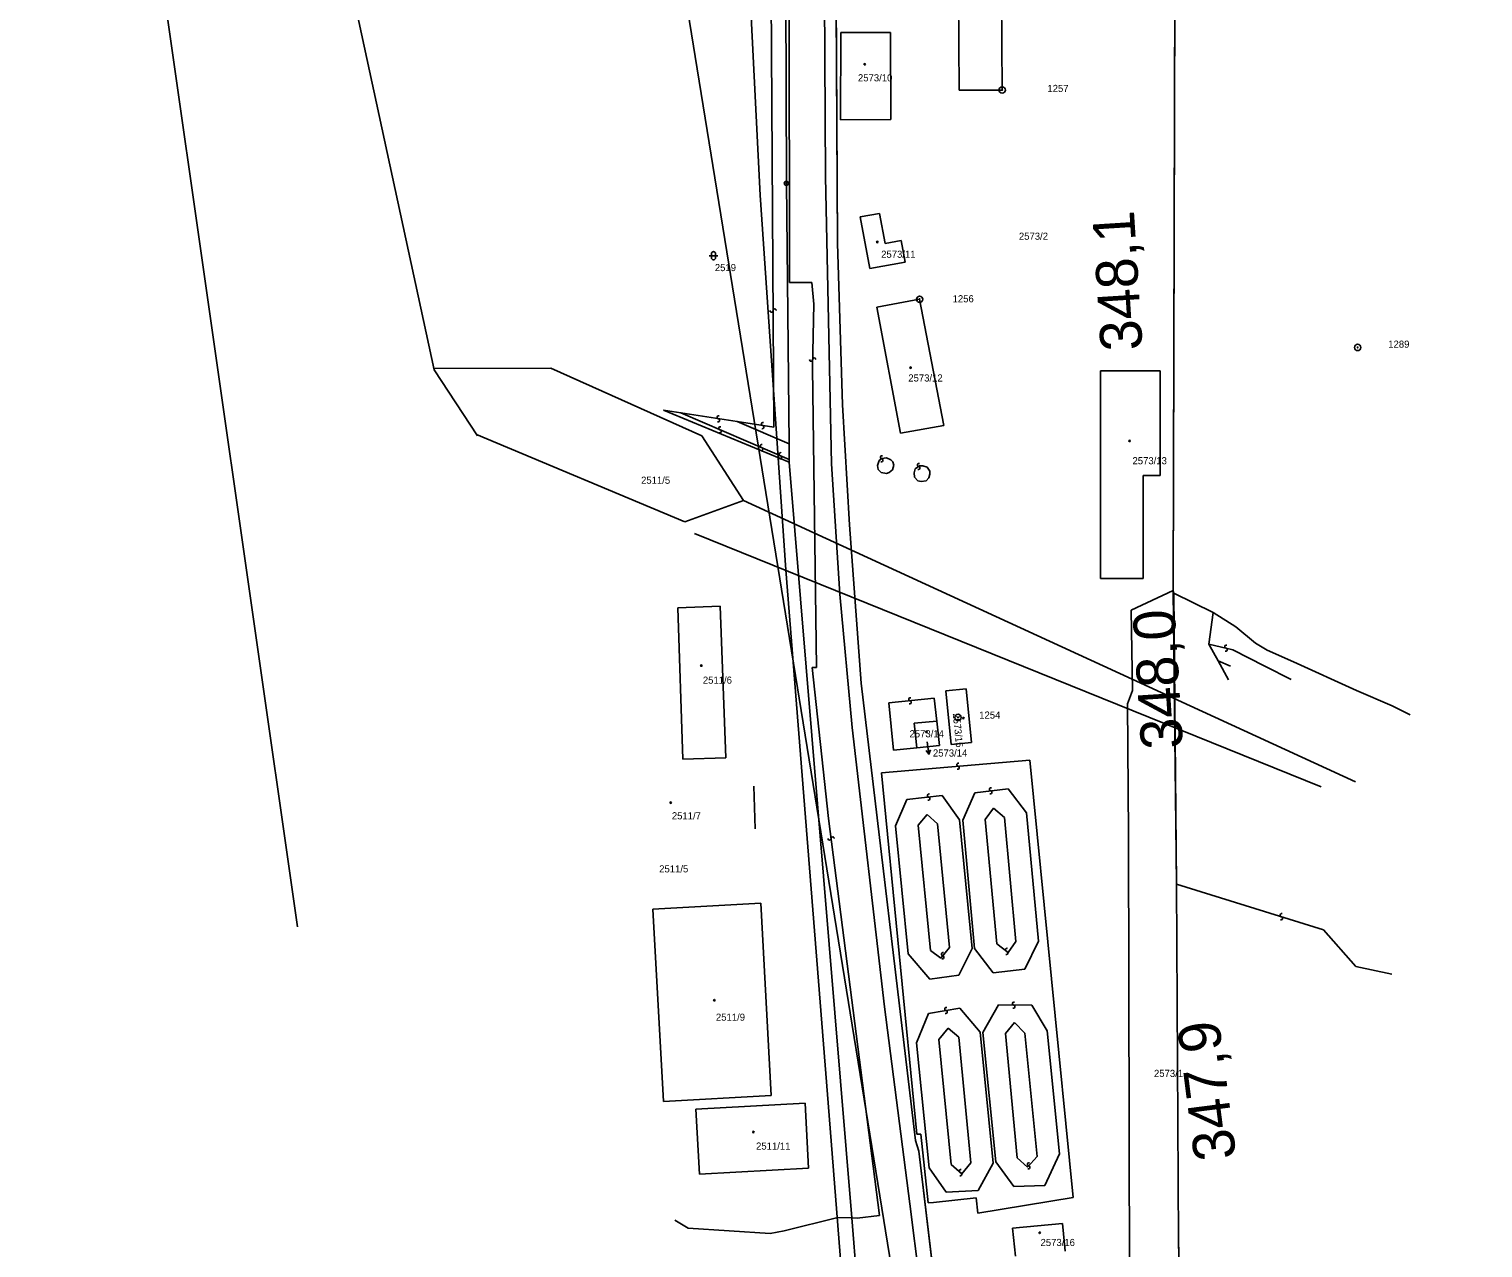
# Model space of a CAD drawing. Extents: x -469926 to -462499, y -1098642 to -1092733.
# Drawn here: x -466074 to -465726.7, y -1096656.9 to -1096365.6 of the extents above; entities that cross this region are included whole.
import ezdxf

# ---------------------------------------------------------------- set-up
doc = ezdxf.new("R2010")
doc.units = 0
for name, color, linetype in [('Vrstva 1', 7, 'Continuous'), ('Vrstva 10', 7, 'Continuous'), ('Vrstva 11', 7, 'Continuous'), ('Vrstva 12', 7, 'Continuous'), ('Vrstva 13', 7, 'Continuous'), ('Vrstva 14', 7, 'Continuous'), ('Vrstva 16', 7, 'Continuous'), ('Vrstva 24', 7, 'Continuous'), ('Vrstva 25', 7, 'Continuous'), ('Vrstva 4', 7, 'Continuous'), ('Vrstva 50', 7, 'Continuous'), ('Vrstva 51', 7, 'Continuous'), ('Vrstva 55', 7, 'Continuous')]:
    doc.layers.add(name, color=color, linetype=linetype)

msp = doc.modelspace()

# ---------------------------------------------------------------- linework, layer by layer
at = {"layer": 'Vrstva 1'}
for p, q in [((-465880.92, -1096416.78), (-465882.4, -1096150.13)), ((-465841.96, -1096312.24), (-465841.54, -1096380.18)), ((-465893.11, -1096402.48), (-465893.29, -1096345.81)), ((-465851.85, -1096380.2), (-465852.02, -1096353.26)), ((-465800.26, -1096355.39), (-465800.67, -1096499.77)), ((-465880.19, -1096387.29), (-465880.12, -1096366.45)), ((-465880.12, -1096366.45), (-465868.26, -1096366.41)), ((-465868.26, -1096366.41), (-465868.17, -1096387.24)), ((-465841.54, -1096380.18), (-465851.85, -1096380.2)), ((-465868.17, -1096387.24), (-465880.19, -1096387.29)), ((-465892.48, -1096464.74), (-465893.11, -1096402.48)), ((-465870.83, -1096409.7), (-465875.49, -1096410.52)), ((-465875.49, -1096410.52), (-465873.15, -1096422.84)), ((-465869.52, -1096416.89), (-465870.83, -1096409.7)), ((-465879.7, -1096455.45), (-465880.92, -1096416.78)), ((-465865.66, -1096416.16), (-465869.52, -1096416.89)), ((-465864.73, -1096421.35), (-465865.66, -1096416.16)), ((-465873.15, -1096422.84), (-465864.73, -1096421.35)), ((-465871.52, -1096432.09), (-465861.28, -1096430.19)), ((-465861.28, -1096430.19), (-465855.51, -1096460.38)), ((-465865.82, -1096462.17), (-465871.52, -1096432.09)), ((-465818.03, -1096496.93), (-465818.02, -1096447.31)), ((-465818.02, -1096447.31), (-465803.81, -1096447.31)), ((-465803.81, -1096447.31), (-465803.81, -1096472.35)), ((-465878, -1096484.1), (-465879.7, -1096455.45)), ((-465892.44, -1096469.15), (-465922.48, -1096456.72)), ((-465904.9, -1096459.44), (-465892.48, -1096464.74)), ((-465855.51, -1096460.38), (-465865.82, -1096462.17)), ((-465892.45, -1096468.49), (-465892.48, -1096464.74)), ((-465892.44, -1096469.15), (-465892.45, -1096468.49)), ((-465877.5, -1096649.76), (-465892.44, -1096469.15)), ((-465803.81, -1096472.35), (-465807.85, -1096472.35)), ((-465807.85, -1096472.35), (-465807.82, -1096496.93)), ((-465875.21, -1096521.97), (-465878, -1096484.1)), ((-465807.82, -1096496.93), (-465818.03, -1096496.93)), ((-465810.71, -1096504.52), (-465800.67, -1096499.77)), ((-465800.67, -1096499.77), (-465800.55, -1096500.45)), ((-465800.55, -1096500.45), (-465799.92, -1096569.98)), ((-465800.55, -1096500.45), (-465791.14, -1096505.07)), ((-465919.06, -1096503.92), (-465908.89, -1096503.57)), ((-465917.83, -1096540.14), (-465919.06, -1096503.92)), ((-465908.89, -1096503.57), (-465907.61, -1096539.77)), ((-465810.41, -1096523.69), (-465810.71, -1096504.52)), ((-465791.14, -1096505.07), (-465792.18, -1096512.63)), ((-465791.14, -1096505.07), (-465785.71, -1096508.48)), ((-465785.71, -1096508.48), (-465781.01, -1096512.42)), ((-465792.18, -1096512.63), (-465789.97, -1096516.59)), ((-465781.01, -1096512.42), (-465778.25, -1096514.09)), ((-465778.25, -1096514.09), (-465771.92, -1096516.81)), ((-465789.97, -1096516.59), (-465787.44, -1096521.15)), ((-465771.92, -1096516.81), (-465756.86, -1096523.69)), ((-465862.23, -1096631.25), (-465875.21, -1096521.97)), ((-465854.98, -1096523.78), (-465850.15, -1096523.31)), ((-465853.72, -1096536.57), (-465854.98, -1096523.78)), ((-465850.15, -1096523.31), (-465848.87, -1096536.1)), ((-465811.63, -1096526.91), (-465810.41, -1096523.69)), ((-465756.86, -1096523.69), (-465748.36, -1096527.4)), ((-465811.33, -1096557.89), (-465811.63, -1096526.91)), ((-465811.33, -1096557.89), (-465811.63, -1096526.91)), ((-465748.36, -1096527.4), (-465744.04, -1096529.52)), ((-465862.56, -1096531.5), (-465857.19, -1096531)), ((-465861.96, -1096537.39), (-465862.56, -1096531.5)), ((-465857.19, -1096531), (-465856.55, -1096536.88)), ((-465856.55, -1096536.88), (-465861.96, -1096537.39)), ((-465848.87, -1096536.1), (-465853.72, -1096536.57)), ((-465907.61, -1096539.77), (-465917.83, -1096540.14)), ((-465900.92, -1096546.57), (-465900.53, -1096556.8)), ((-465810.96, -1096744.58), (-465811.33, -1096557.89)), ((-465799.92, -1096569.98), (-465799.38, -1096655.08)), ((-465925.04, -1096575.98), (-465899.22, -1096574.55)), ((-465922.5, -1096621.89), (-465925.04, -1096575.98)), ((-465899.22, -1096574.55), (-465896.74, -1096620.53)), ((-465896.74, -1096620.53), (-465922.5, -1096621.89)), ((-465914.75, -1096623.75), (-465888.63, -1096622.3)), ((-465888.63, -1096622.3), (-465887.83, -1096637.84)), ((-465913.89, -1096639.26), (-465914.75, -1096623.75)), ((-465861.43, -1096633.83), (-465862.23, -1096631.25)), ((-465855.27, -1096685.91), (-465861.43, -1096633.83)), ((-465887.83, -1096637.84), (-465913.89, -1096639.26)), ((-465919.76, -1096650.26), (-465916.6, -1096652.22)), ((-465893.66, -1096652.88), (-465880.83, -1096649.67)), ((-465880.83, -1096649.67), (-465877.5, -1096649.76)), ((-465873.17, -1096702.18), (-465877.5, -1096649.76)), ((-465916.6, -1096652.22), (-465896.96, -1096653.49)), ((-465896.96, -1096653.49), (-465893.66, -1096652.88)), ((-465839.04, -1096652.24), (-465827.17, -1096651.08)), ((-465838.39, -1096658.87), (-465839.04, -1096652.24)), ((-465827.17, -1096651.08), (-465826.52, -1096657.71)), ((-465799.38, -1096655.08), (-465797.68, -1096743.44))]:
    msp.add_line(p, q, dxfattribs=at)
at = {"layer": 'Vrstva 10'}
for p, q in [((-465884.47, -1096284.81), (-465883.73, -1096400.9)), ((-465883.73, -1096400.9), (-465882.36, -1096469.49)), ((-465882.36, -1096469.49), (-465880.36, -1096500.64)), ((-465880.36, -1096500.64), (-465877.42, -1096532.56)), ((-465877.42, -1096532.56), (-465869.67, -1096599.33)), ((-465869.67, -1096599.33), (-465863.64, -1096646.38)), ((-465863.64, -1096646.38), (-465853.4, -1096727.1))]:
    msp.add_line(p, q, dxfattribs=at)
at = {"layer": 'Vrstva 11'}
for points in [[(-465726.68, -1095986.97), (-465750.69, -1096042.89), (-465756.4, -1096060.74), (-465774.69, -1096151.27), (-465798.39, -1096267.46), (-465800.54, -1096267.43), (-465803.81, -1096291.77), (-465800.26, -1096355.39), (-465800.67, -1096499.77), (-465799.92, -1096569.98), (-465799.38, -1096655.08), (-465797.68, -1096743.44)], [(-465855.27, -1096685.91), (-465861.43, -1096633.83), (-465862.23, -1096631.25), (-465875.21, -1096521.97), (-465878, -1096484.1), (-465879.7, -1096455.45), (-465880.92, -1096416.78), (-465880.92, -1096416.78), (-465880.92, -1096416.78), (-465880.92, -1096416.78), (-465880.92, -1096416.78), (-465880.92, -1096416.78), (-465880.92, -1096416.78), (-465882.4, -1096150.13), (-465882.66, -1096120), (-465881.38, -1096097.97)]]:
    msp.add_lwpolyline(points, dxfattribs=at)
at = {"layer": 'Vrstva 12'}
for p, q in [((-465899.34, -1096405.28), (-465907.04, -1096253.31)), ((-465893.25, -1096494.86), (-465899.34, -1096405.28)), ((-465765.33, -1096546.73), (-465915.06, -1096486.17)), ((-465882.88, -1096625.26), (-465893.25, -1096494.86)), ((-465876.31, -1096709.48), (-465882.88, -1096625.26))]:
    msp.add_line(p, q, dxfattribs=at)
at = {"layer": 'Vrstva 13'}
msp.add_line((-465952.03, -1096142.86), (-465857.17, -1096728.32), dxfattribs=at)
at = {"layer": 'Vrstva 14'}
for p, q in [((-466074.05, -1096000.07), (-465977.23, -1096447.03)), ((-466050.4, -1096296.94), (-466009.89, -1096580.19)), ((-465977.3, -1096446.71), (-465949.42, -1096446.66)), ((-465977.23, -1096447.03), (-465966.92, -1096462.87)), ((-465949.42, -1096446.66), (-465913.34, -1096462.87)), ((-465967.17, -1096462.49), (-465917.38, -1096483.4)), ((-465913.34, -1096462.87), (-465903.37, -1096478.27)), ((-465917.38, -1096483.4), (-465903.37, -1096478.27)), ((-465903.37, -1096478.27), (-465757.16, -1096545.53))]:
    msp.add_line(p, q, dxfattribs=at)
at = {"layer": 'Vrstva 16'}
msp.add_line((-465859.5, -1096535.97), (-465859.04, -1096538.94), dxfattribs=at)
msp.add_lwpolyline([(-465858.7, -1096537.87), (-465859.04, -1096538.94), (-465859.69, -1096538.02)], dxfattribs=at)
at = {"layer": 'Vrstva 24'}
for centre, radius in [((-465841.54, -1096380.18), 0.75), ((-465841.54, -1096380.18), 0.1), ((-465893.11, -1096402.48), 0.5), ((-465893.11, -1096402.48), 0.1), ((-465861.28, -1096430.19), 0.75), ((-465861.28, -1096430.19), 0.1), ((-465756.61, -1096441.71), 0.75), ((-465756.61, -1096441.71), 0.1), ((-465852.1, -1096530.14), 0.75), ((-465852.1, -1096530.14), 0.1)]:
    msp.add_circle(centre, radius, dxfattribs=at)
at = {"layer": 'Vrstva 25'}
for p, q in [((-465911.52, -1096419.78), (-465909.52, -1096419.78)), ((-465911.02, -1096419.28), (-465911.02, -1096420.28)), ((-465910.02, -1096419.28), (-465910.02, -1096420.28))]:
    msp.add_line(p, q, dxfattribs=at)
for centre in [(-465874.37, -1096374.02), (-465871.38, -1096416.51), (-465863.44, -1096446.55), (-465811.11, -1096464.05), (-465913.43, -1096517.74), (-465850.8, -1096530.29), (-465859.63, -1096533.59), (-465920.73, -1096550.5), (-465910.31, -1096597.72), (-465900.97, -1096629.23), (-465832.57, -1096653.31)]:
    msp.add_circle(centre, 0.175, dxfattribs=at)
for centre, start, end in [((-465910.52, -1096419.28), 0, 180), ((-465910.52, -1096420.28), 180, 0)]:
    msp.add_arc(centre, 0.5, start, end, dxfattribs=at)
at = {"layer": 'Vrstva 4'}
for p, q in [((-465892.39, -1096426.15), (-465892.59, -1096273.45)), ((-465896.1, -1096460.8), (-465896.82, -1096351.3)), ((-465886.99, -1096426.17), (-465892.39, -1096426.15)), ((-465886.57, -1096431.34), (-465886.99, -1096426.17)), ((-465886.87, -1096446.56), (-465886.57, -1096431.34)), ((-465885.92, -1096518.2), (-465886.87, -1096446.56)), ((-465922.48, -1096456.72), (-465918.32, -1096457.36)), ((-465918.32, -1096457.36), (-465904.9, -1096459.44)), ((-465918.32, -1096457.36), (-465892.45, -1096468.49)), ((-465904.9, -1096459.44), (-465896.1, -1096460.8)), ((-465871.31, -1096469.91), (-465870.92, -1096468.75)), ((-465871.14, -1096470.84), (-465871.31, -1096469.91)), ((-465870.92, -1096468.75), (-465870.26, -1096468.26)), ((-465870.26, -1096468.26), (-465869.2, -1096468.12)), ((-465869.2, -1096468.12), (-465868.15, -1096468.56)), ((-465868.15, -1096468.56), (-465867.66, -1096469.08)), ((-465867.47, -1096469.85), (-465867.74, -1096470.93)), ((-465867.66, -1096469.08), (-465867.47, -1096469.85)), ((-465870.42, -1096471.59), (-465871.14, -1096470.84)), ((-465869.2, -1096471.82), (-465870.42, -1096471.59)), ((-465868.57, -1096471.6), (-465869.2, -1096471.82)), ((-465867.74, -1096470.93), (-465868.57, -1096471.6)), ((-465862.6, -1096471.69), (-465862.3, -1096470.75)), ((-465862.48, -1096472.68), (-465862.6, -1096471.69)), ((-465861.67, -1096473.58), (-465862.48, -1096472.68)), ((-465862.3, -1096470.75), (-465861.31, -1096470.02)), ((-465861.31, -1096470.02), (-465860.54, -1096469.97)), ((-465860.54, -1096469.97), (-465859.49, -1096470.36)), ((-465859.04, -1096472.91), (-465859.67, -1096473.55)), ((-465859.49, -1096470.36), (-465858.83, -1096471.26)), ((-465858.82, -1096472.03), (-465859.04, -1096472.91)), ((-465858.83, -1096471.26), (-465858.82, -1096472.03)), ((-465860.88, -1096473.71), (-465861.67, -1096473.58)), ((-465859.67, -1096473.55), (-465860.88, -1096473.71)), ((-465792.18, -1096512.63), (-465786.46, -1096513.95)), ((-465786.46, -1096513.95), (-465778.78, -1096517.92)), ((-465883.03, -1096554.29), (-465886.95, -1096518.17)), ((-465886.95, -1096518.17), (-465885.92, -1096518.2)), ((-465789.97, -1096516.59), (-465786.99, -1096517.88)), ((-465778.78, -1096517.92), (-465772.5, -1096521.07)), ((-465868.62, -1096526.67), (-465857.78, -1096525.55)), ((-465867.49, -1096537.96), (-465868.62, -1096526.67)), ((-465857.78, -1096525.55), (-465857.19, -1096531)), ((-465861.96, -1096537.39), (-465867.49, -1096537.96)), ((-465870.34, -1096543.35), (-465834.92, -1096540.35)), ((-465834.92, -1096540.35), (-465824.62, -1096644.88)), ((-465861.91, -1096629.71), (-465870.34, -1096543.35)), ((-465867.07, -1096556.04), (-465864.34, -1096549.74)), ((-465864.34, -1096549.74), (-465855.88, -1096548.82)), ((-465855.88, -1096548.82), (-465851.71, -1096554.65)), ((-465850.98, -1096554.67), (-465848.04, -1096548.15)), ((-465848.04, -1096548.15), (-465840.12, -1096547.18)), ((-465840.12, -1096547.18), (-465835.75, -1096552.96)), ((-465845.62, -1096554.5), (-465843.63, -1096551.86)), ((-465843.63, -1096551.86), (-465841.02, -1096554.02)), ((-465835.75, -1096552.96), (-465832.87, -1096583.57)), ((-465870.88, -1096649.19), (-465883.03, -1096554.29)), ((-465864.03, -1096586.67), (-465867.07, -1096556.04)), ((-465861.61, -1096555.87), (-465859.45, -1096553.37)), ((-465858.67, -1096585.84), (-465861.61, -1096555.87)), ((-465859.45, -1096553.37), (-465857.01, -1096555.53)), ((-465857.01, -1096555.53), (-465854.16, -1096585.14)), ((-465851.71, -1096554.65), (-465848.74, -1096585.35)), ((-465848.16, -1096585.37), (-465850.98, -1096554.67)), ((-465842.84, -1096584.28), (-465845.62, -1096554.5)), ((-465841.02, -1096554.02), (-465838.26, -1096583.71)), ((-465799.92, -1096569.98), (-465764.74, -1096580.9)), ((-465764.74, -1096580.9), (-465757.07, -1096589.65)), ((-465840.09, -1096586.35), (-465842.84, -1096584.28)), ((-465838.26, -1096583.71), (-465840.09, -1096586.35)), ((-465832.87, -1096583.57), (-465836.16, -1096590.28)), ((-465858.82, -1096592.69), (-465864.03, -1096586.67)), ((-465856.23, -1096587.67), (-465858.67, -1096585.84)), ((-465854.16, -1096585.14), (-465856.23, -1096587.67)), ((-465848.74, -1096585.35), (-465851.93, -1096591.75)), ((-465843.7, -1096591.17), (-465848.16, -1096585.37)), ((-465836.16, -1096590.28), (-465843.7, -1096591.17)), ((-465757.07, -1096589.65), (-465748.43, -1096591.51)), ((-465851.93, -1096591.75), (-465858.82, -1096592.69)), ((-465861.98, -1096607.88), (-465859.18, -1096600.87)), ((-465859.18, -1096600.87), (-465851.65, -1096599.64)), ((-465851.65, -1096599.64), (-465846.84, -1096605.36)), ((-465846.15, -1096605.42), (-465842.42, -1096598.86)), ((-465842.42, -1096598.86), (-465834.44, -1096598.93)), ((-465834.44, -1096598.93), (-465830.79, -1096605.01)), ((-465856.69, -1096607.13), (-465854.49, -1096604.4)), ((-465854.49, -1096604.4), (-465851.94, -1096606.57)), ((-465846.84, -1096605.36), (-465843.67, -1096636.65)), ((-465840.73, -1096605.71), (-465838.61, -1096603.07)), ((-465838.61, -1096603.07), (-465836.11, -1096605.57)), ((-465830.79, -1096605.01), (-465827.85, -1096634.43)), ((-465859, -1096637.78), (-465861.98, -1096607.88)), ((-465853.74, -1096637), (-465856.69, -1096607.13)), ((-465851.94, -1096606.57), (-465849.01, -1096636.61)), ((-465843.06, -1096636.38), (-465846.15, -1096605.42)), ((-465837.94, -1096635.38), (-465840.73, -1096605.71)), ((-465836.11, -1096605.57), (-465833.18, -1096635.07)), ((-465861.01, -1096629.72), (-465861.91, -1096629.71)), ((-465859.24, -1096646.11), (-465861.01, -1096629.72)), ((-465849.01, -1096636.61), (-465851.2, -1096639.21)), ((-465843.67, -1096636.65), (-465847.29, -1096643.23)), ((-465838.77, -1096642.25), (-465843.06, -1096636.38)), ((-465835.5, -1096637.62), (-465837.94, -1096635.38)), ((-465833.18, -1096635.07), (-465835.5, -1096637.62)), ((-465827.85, -1096634.43), (-465831.36, -1096641.98)), ((-465854.94, -1096643.62), (-465859, -1096637.78)), ((-465851.2, -1096639.21), (-465853.74, -1096637)), ((-465847.29, -1096643.23), (-465854.94, -1096643.62)), ((-465831.36, -1096641.98), (-465838.77, -1096642.25)), ((-465857.92, -1096646.05), (-465859.24, -1096646.11)), ((-465847.8, -1096644.93), (-465857.92, -1096646.05)), ((-465847.35, -1096648.6), (-465847.8, -1096644.93)), ((-465824.62, -1096644.88), (-465847.35, -1096648.6)), ((-465877.5, -1096649.76), (-465876.22, -1096649.79)), ((-465876.22, -1096649.79), (-465870.88, -1096649.19))]:
    msp.add_line(p, q, dxfattribs=at)
at = {"layer": 'Vrstva 51'}
for centre, radius, start, end in [((-465896.66, -1096432.93), 0.376, 176.8404, 3.1515), ((-465895.91, -1096432.88), 0.377, 356.1643, 183.8275), ((-465887.21, -1096444.64), 0.376, 176.8404, 3.1515), ((-465886.46, -1096444.6), 0.377, 356.1643, 183.8275), ((-465909.27, -1096458.38), 0.376, 71.7204, 258.0315), ((-465909.42, -1096459.12), 0.377, 251.0443, 78.7075), ((-465908.9, -1096461.01), 0.376, 71.7204, 258.0315), ((-465909.06, -1096461.75), 0.377, 251.0443, 78.7075), ((-465898.68, -1096460.02), 0.376, 71.7204, 258.0315), ((-465898.84, -1096460.76), 0.377, 251.0443, 78.7075), ((-465898.97, -1096465.28), 0.376, 71.7204, 258.0315), ((-465899.12, -1096466.02), 0.377, 251.0443, 78.7075), ((-465894.48, -1096467.22), 0.376, 71.7204, 258.0315), ((-465894.63, -1096467.95), 0.377, 251.0443, 78.7075), ((-465870.27, -1096467.96), 0.376, 71.7204, 258.0315), ((-465870.42, -1096468.69), 0.377, 251.0443, 78.7075), ((-465861.43, -1096469.8), 0.376, 71.7204, 258.0315), ((-465861.58, -1096470.53), 0.377, 251.0443, 78.7075), ((-465787.98, -1096513.21), 0.376, 71.7204, 258.0315), ((-465788.13, -1096513.95), 0.377, 251.0443, 78.7075), ((-465863.51, -1096525.78), 0.376, 71.7204, 258.0315), ((-465863.66, -1096526.52), 0.377, 251.0443, 78.7075), ((-465851.99, -1096541.43), 0.376, 71.7204, 258.0315), ((-465852.15, -1096542.17), 0.377, 251.0443, 78.7075), ((-465859.04, -1096548.8), 0.376, 71.7204, 258.0315), ((-465859.19, -1096549.54), 0.377, 251.0443, 78.7075), ((-465844.24, -1096547.33), 0.376, 71.7204, 258.0315), ((-465844.39, -1096548.06), 0.377, 251.0443, 78.7075), ((-465882.79, -1096559.1), 0.376, 176.8404, 3.1515), ((-465882.04, -1096559.06), 0.377, 356.1643, 183.8275), ((-465774.79, -1096577.39), 0.376, 71.7204, 258.0315), ((-465774.94, -1096578.13), 0.377, 251.0443, 78.7075), ((-465855.67, -1096586.71), 0.376, 71.7204, 258.0315), ((-465855.82, -1096587.45), 0.377, 251.0443, 78.7075), ((-465840.41, -1096585.68), 0.376, 71.7204, 258.0315), ((-465840.57, -1096586.42), 0.377, 251.0443, 78.7075), ((-465838.7, -1096598.52), 0.376, 71.7204, 258.0315), ((-465854.9, -1096599.82), 0.376, 71.7204, 258.0315), ((-465855.05, -1096600.55), 0.377, 251.0443, 78.7075), ((-465838.85, -1096599.26), 0.377, 251.0443, 78.7075), ((-465835.13, -1096636.93), 0.376, 71.7204, 258.0315), ((-465851.43, -1096638.57), 0.376, 71.7204, 258.0315), ((-465851.58, -1096639.31), 0.377, 251.0443, 78.7075), ((-465835.28, -1096637.67), 0.377, 251.0443, 78.7075)]:
    msp.add_arc(centre, radius, start, end, dxfattribs=at)

# ---------------------------------------------------------------- texts
at = {"layer": 'Vrstva 50'}
for s, p in [('2573/10', (-465876, -1096378.11)), ('1257', (-465830.74, -1096380.65)), ('2573/2', (-465837.55, -1096415.97)), ('2573/11', (-465870.46, -1096420.28)), ('2519', (-465910.2, -1096423.47)), ('1256', (-465853.39, -1096430.92)), ('1289', (-465749.3, -1096441.77)), ('2573/12', (-465863.98, -1096449.85)), ('2573/13', (-465810.41, -1096469.63)), ('2511/5', (-465927.83, -1096474.29)), ('2511/6', (-465913.06, -1096522.07)), ('1254', (-465847.03, -1096530.42)), ('2573/14', (-465863.68, -1096534.89)), ('2573/14', (-465858.09, -1096539.49)), ('2511/7', (-465920.47, -1096554.49)), ('2511/5', (-465923.5, -1096567.18)), ('2511/9', (-465909.94, -1096602.62)), ('2573/1', (-465805.27, -1096616.06)), ('2511/11', (-465900.35, -1096633.43)), ('2573/16', (-465832.38, -1096656.47))]:
    msp.add_text(s, height=1.7, dxfattribs=at).set_placement(p)
msp.add_text('2573/15', height=1.7, rotation=275.652, dxfattribs=at).set_placement((-465853.35, -1096529.21))
at = {"layer": 'Vrstva 55'}
for s, rotation, p in [('348,1', 93.6074, (-465807.97, -1096442.22)), ('348,0', 93.6074, (-465798.3, -1096537.42)), ('347,9', 97.294, (-465785.58, -1096635.36))]:
    msp.add_text(s, height=10, rotation=rotation, dxfattribs=at).set_placement(p)

doc.saveas('drawing.dxf')
